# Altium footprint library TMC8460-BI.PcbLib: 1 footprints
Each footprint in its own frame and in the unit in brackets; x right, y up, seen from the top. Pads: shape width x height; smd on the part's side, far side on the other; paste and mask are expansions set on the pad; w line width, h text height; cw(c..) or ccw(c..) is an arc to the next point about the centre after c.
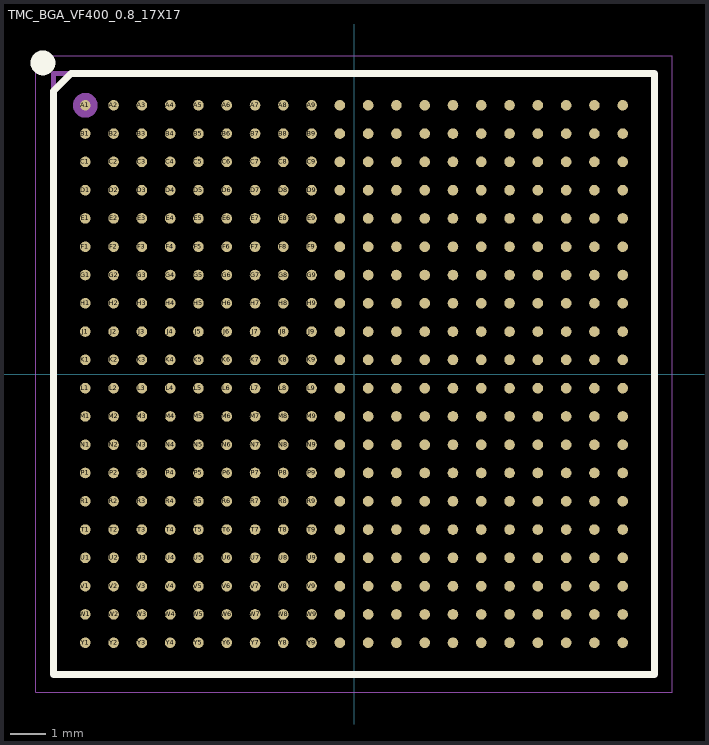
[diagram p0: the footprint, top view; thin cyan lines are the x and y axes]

## TMC_BGA_VF400_0.8_17X17 [mm]
pads (400):
  round 0.3 smd: A1(-7.6,7.6) A2(-6.8,7.6) A3(-6,7.6) A4(-5.2,7.6) A5(-4.4,7.6) A6(-3.6,7.6) A7(-2.8,7.6) A8(-2,7.6) A9(-1.2,7.6) A10(-0.4,7.6) A11(0.4,7.6) A12(1.2,7.6) A13(2,7.6) A14(2.8,7.6) A15(3.6,7.6) A16(4.4,7.6) A17(5.2,7.6) A18(6,7.6) A19(6.8,7.6) A20(7.6,7.6) B1(-7.6,6.8) B2(-6.8,6.8) B3(-6,6.8) B4(-5.2,6.8) B5(-4.4,6.8) B6(-3.6,6.8) B7(-2.8,6.8) B8(-2,6.8) B9(-1.2,6.8) B10(-0.4,6.8) B11(0.4,6.8) B12(1.2,6.8) B13(2,6.8) B14(2.8,6.8) B15(3.6,6.8) B16(4.4,6.8) B17(5.2,6.8) B18(6,6.8) B19(6.8,6.8) B20(7.6,6.8) C1(-7.6,6) C2(-6.8,6) C3(-6,6) C4(-5.2,6) C5(-4.4,6) C6(-3.6,6) C7(-2.8,6) C8(-2,6) C9(-1.2,6) C10(-0.4,6) C11(0.4,6) C12(1.2,6) C13(2,6) C14(2.8,6) C15(3.6,6) C16(4.4,6) C17(5.2,6) C18(6,6) C19(6.8,6) C20(7.6,6) D1(-7.6,5.2) D2(-6.8,5.2) D3(-6,5.2) D4(-5.2,5.2) D5(-4.4,5.2) D6(-3.6,5.2) D7(-2.8,5.2) D8(-2,5.2) D9(-1.2,5.2) D10(-0.4,5.2) D11(0.4,5.2) D12(1.2,5.2) D13(2,5.2) D14(2.8,5.2) D15(3.6,5.2) D16(4.4,5.2) D17(5.2,5.2) D18(6,5.2) D19(6.8,5.2) D20(7.6,5.2) E1(-7.6,4.4) E2(-6.8,4.4) E3(-6,4.4) E4(-5.2,4.4) E5(-4.4,4.4) E6(-3.6,4.4) E7(-2.8,4.4) E8(-2,4.4) E9(-1.2,4.4) E10(-0.4,4.4) E11(0.4,4.4) E12(1.2,4.4) E13(2,4.4) E14(2.8,4.4) E15(3.6,4.4) E16(4.4,4.4) E17(5.2,4.4) E18(6,4.4) E19(6.8,4.4) E20(7.6,4.4) F1(-7.6,3.6) F2(-6.8,3.6) F3(-6,3.6) F4(-5.2,3.6) F5(-4.4,3.6) F6(-3.6,3.6) F7(-2.8,3.6) F8(-2,3.6) F9(-1.2,3.6) F10(-0.4,3.6) F11(0.4,3.6) F12(1.2,3.6) F13(2,3.6) F14(2.8,3.6) F15(3.6,3.6) F16(4.4,3.6) F17(5.2,3.6) F18(6,3.6) F19(6.8,3.6) F20(7.6,3.6) G1(-7.6,2.8) G2(-6.8,2.8) G3(-6,2.8) G4(-5.2,2.8) G5(-4.4,2.8) G6(-3.6,2.8) G7(-2.8,2.8) G8(-2,2.8) G9(-1.2,2.8) G10(-0.4,2.8) G11(0.4,2.8) G12(1.2,2.8) G13(2,2.8) G14(2.8,2.8) G15(3.6,2.8) G16(4.4,2.8) G17(5.2,2.8) G18(6,2.8) G19(6.8,2.8) G20(7.6,2.8) H1(-7.6,2) H2(-6.8,2) H3(-6,2) H4(-5.2,2) H5(-4.4,2) H6(-3.6,2) H7(-2.8,2) H8(-2,2) H9(-1.2,2) H10(-0.4,2) H11(0.4,2) H12(1.2,2) H13(2,2) H14(2.8,2) H15(3.6,2) H16(4.4,2) H17(5.2,2) H18(6,2) H19(6.8,2) H20(7.6,2) J1(-7.6,1.2) J2(-6.8,1.2) J3(-6,1.2) J4(-5.2,1.2) J5(-4.4,1.2) J6(-3.6,1.2) J7(-2.8,1.2) J8(-2,1.2) J9(-1.2,1.2) J10(-0.4,1.2) J11(0.4,1.2) J12(1.2,1.2) J13(2,1.2) J14(2.8,1.2) J15(3.6,1.2) J16(4.4,1.2) J17(5.2,1.2) J18(6,1.2) J19(6.8,1.2) J20(7.6,1.2) K1(-7.6,0.4) K2(-6.8,0.4) K3(-6,0.4) K4(-5.2,0.4) K5(-4.4,0.4) K6(-3.6,0.4) K7(-2.8,0.4) K8(-2,0.4) K9(-1.2,0.4) K10(-0.4,0.4) K11(0.4,0.4) K12(1.2,0.4) K13(2,0.4) K14(2.8,0.4) K15(3.6,0.4) K16(4.4,0.4) K17(5.2,0.4) K18(6,0.4) K19(6.8,0.4) K20(7.6,0.4) L1(-7.6,-0.4) L2(-6.8,-0.4) L3(-6,-0.4) L4(-5.2,-0.4) L5(-4.4,-0.4) L6(-3.6,-0.4) L7(-2.8,-0.4) L8(-2,-0.4) L9(-1.2,-0.4) L10(-0.4,-0.4) L11(0.4,-0.4) L12(1.2,-0.4) L13(2,-0.4) L14(2.8,-0.4) L15(3.6,-0.4) L16(4.4,-0.4) L17(5.2,-0.4) L18(6,-0.4) L19(6.8,-0.4) L20(7.6,-0.4) M1(-7.6,-1.2) M2(-6.8,-1.2) M3(-6,-1.2) M4(-5.2,-1.2) M5(-4.4,-1.2) M6(-3.6,-1.2) M7(-2.8,-1.2) M8(-2,-1.2) M9(-1.2,-1.2) M10(-0.4,-1.2) M11(0.4,-1.2) M12(1.2,-1.2) M13(2,-1.2) M14(2.8,-1.2) M15(3.6,-1.2) M16(4.4,-1.2) M17(5.2,-1.2) M18(6,-1.2) M19(6.8,-1.2) M20(7.6,-1.2) N1(-7.6,-2) N2(-6.8,-2) N3(-6,-2) N4(-5.2,-2) N5(-4.4,-2) N6(-3.6,-2) N7(-2.8,-2) N8(-2,-2) N9(-1.2,-2) N10(-0.4,-2) N11(0.4,-2) N12(1.2,-2) N13(2,-2) N14(2.8,-2) N15(3.6,-2) N16(4.4,-2) N17(5.2,-2) N18(6,-2) N19(6.8,-2) N20(7.6,-2) P1(-7.6,-2.8) P2(-6.8,-2.8) P3(-6,-2.8) P4(-5.2,-2.8) P5(-4.4,-2.8) P6(-3.6,-2.8) P7(-2.8,-2.8) P8(-2,-2.8) P9(-1.2,-2.8) P10(-0.4,-2.8) P11(0.4,-2.8) P12(1.2,-2.8) P13(2,-2.8) P14(2.8,-2.8) P15(3.6,-2.8) P16(4.4,-2.8) P17(5.2,-2.8) P18(6,-2.8) P19(6.8,-2.8) P20(7.6,-2.8) R1(-7.6,-3.6) R2(-6.8,-3.6) R3(-6,-3.6) R4(-5.2,-3.6) R5(-4.4,-3.6) R6(-3.6,-3.6) R7(-2.8,-3.6) R8(-2,-3.6) R9(-1.2,-3.6) R10(-0.4,-3.6) R11(0.4,-3.6) R12(1.2,-3.6) R13(2,-3.6) R14(2.8,-3.6) R15(3.6,-3.6) R16(4.4,-3.6) R17(5.2,-3.6) R18(6,-3.6) R19(6.8,-3.6) R20(7.6,-3.6) T1(-7.6,-4.4) T2(-6.8,-4.4) T3(-6,-4.4) T4(-5.2,-4.4) T5(-4.4,-4.4) T6(-3.6,-4.4) T7(-2.8,-4.4) T8(-2,-4.4) T9(-1.2,-4.4) T10(-0.4,-4.4) T11(0.4,-4.4) T12(1.2,-4.4) T13(2,-4.4) T14(2.8,-4.4) T15(3.6,-4.4) T16(4.4,-4.4) T17(5.2,-4.4) T18(6,-4.4) T19(6.8,-4.4) T20(7.6,-4.4) U1(-7.6,-5.2) U2(-6.8,-5.2) U3(-6,-5.2) U4(-5.2,-5.2) U5(-4.4,-5.2) U6(-3.6,-5.2) U7(-2.8,-5.2) U8(-2,-5.2) U9(-1.2,-5.2) U10(-0.4,-5.2) U11(0.4,-5.2) U12(1.2,-5.2) U13(2,-5.2) U14(2.8,-5.2) U15(3.6,-5.2) U16(4.4,-5.2) U17(5.2,-5.2) U18(6,-5.2) U19(6.8,-5.2) U20(7.6,-5.2) V1(-7.6,-6) V2(-6.8,-6) V3(-6,-6) V4(-5.2,-6) V5(-4.4,-6) V6(-3.6,-6) V7(-2.8,-6) V8(-2,-6) V9(-1.2,-6) V10(-0.4,-6) V11(0.4,-6) V12(1.2,-6) V13(2,-6) V14(2.8,-6) V15(3.6,-6) V16(4.4,-6) V17(5.2,-6) V18(6,-6) V19(6.8,-6) V20(7.6,-6) W1(-7.6,-6.8) W2(-6.8,-6.8) W3(-6,-6.8) W4(-5.2,-6.8) W5(-4.4,-6.8) W6(-3.6,-6.8) W7(-2.8,-6.8) W8(-2,-6.8) W9(-1.2,-6.8) W10(-0.4,-6.8) W11(0.4,-6.8) W12(1.2,-6.8) W13(2,-6.8) W14(2.8,-6.8) W15(3.6,-6.8) W16(4.4,-6.8) W17(5.2,-6.8) W18(6,-6.8) W19(6.8,-6.8) W20(7.6,-6.8) Y1(-7.6,-7.6) Y2(-6.8,-7.6) Y3(-6,-7.6) Y4(-5.2,-7.6) Y5(-4.4,-7.6) Y6(-3.6,-7.6) Y7(-2.8,-7.6) Y8(-2,-7.6) Y9(-1.2,-7.6) Y10(-0.4,-7.6) Y11(0.4,-7.6) Y12(1.2,-7.6) Y13(2,-7.6) Y14(2.8,-7.6) Y15(3.6,-7.6) Y16(4.4,-7.6) Y17(5.2,-7.6) Y18(6,-7.6) Y19(6.8,-7.6) Y20(7.6,-7.6)
L26-Silk Screen Top (Multiple PADS layers...):
  circle w0.5: c-8.8,8.8 r0.1
  lines w0.2: -8.5,-8.5 8.5,-8.5 8.5,8.5 -8,8.5 -8.5,8 -8.5,-8.5
L13:
  circle w0.5: c-7.6,7.6 r0.1
  lines w0.15: -8.5,-8.5 -8.5,8.5 8.5,8.5 8.5,-8.5 -8.5,-8.5
L15 (Multiple PADS layers...):
  lines w0.01: -9,-9 -9,9 9,9 9,-9 -9,-9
